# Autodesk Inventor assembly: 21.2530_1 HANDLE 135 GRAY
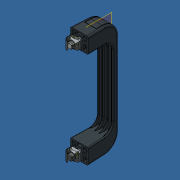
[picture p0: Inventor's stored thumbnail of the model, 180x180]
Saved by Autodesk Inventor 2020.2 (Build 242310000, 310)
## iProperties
Created: 2020-07
Part Number: 21.2530_1 HANDLE 135 GRAY
Document SubType Name: Assembly
Designer: amoles
Author: amoles
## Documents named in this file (5)
- Y:\INVENTOR LIBRARIES\PARTS LIBRARY\HANDLES LOCKS STOPS\21.2530_7 HANDLE 135 GRAY.iam
- Y:\INVENTOR LIBRARIES\PARTS LIBRARY\HANDLES LOCKS STOPS\SUBCOMPONENTS\21.2530_1 HANDLE 135 GRAY.ipt
- Y:\INVENTOR LIBRARIES\PARTS LIBRARY\FASTENING ELEMENTS\SCREWS CAP\21.1202 M8X20.ipt
- Y:\INVENTOR LIBRARIES\PARTS LIBRARY\HANDLES LOCKS STOPS\SUBCOMPONENTS\21.2530_1 HANDLE 135 GRAY END CAP.ipt
- Y:\INVENTOR LIBRARIES\PARTS LIBRARY\FASTENING ELEMENTS\NUTS\21.1351_2 M8 SQUARE NUT POS FXG.ipt
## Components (7 placed, 4 different names)
1. 21.2530_1 HANDLE 135 GRAY:1 — Insert:1, Insert:2, Insert:3, Insert:4, Mate:1, Mate:2, Flush:1, Mate:3, Mate:4, Flush:2
2. 21.1202  M8 x 20:1 — Insert:1
3. 21.1202  M8 x 20:2 — Insert:2
4. 21.1351_2 M8 SQUARE NUT POS FXG:1 — Insert:3
5. 21.1351_2 M8 SQUARE NUT POS FXG:2 — Insert:4
6. 21.2530_1 HANDLE 135 GRAY END CAP:1 — Mate:1, Mate:2, Flush:1
7. 21.2530_1 HANDLE 135 GRAY END CAP:2 — Mate:3, Mate:4, Flush:2
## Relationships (10: Insert 4, Mate 4, Flush 2)
- Insert:1: 21.2530_1 HANDLE 135 GRAY:1 ↔ 21.1202  M8 x 20:1
- Insert:2: 21.2530_1 HANDLE 135 GRAY:1 ↔ 21.1202  M8 x 20:2
- Insert:3: 21.2530_1 HANDLE 135 GRAY:1 ↔ 21.1351_2 M8 SQUARE NUT POS FXG:1
- Insert:4: 21.2530_1 HANDLE 135 GRAY:1 ↔ 21.1351_2 M8 SQUARE NUT POS FXG:2
- Mate:1: 21.2530_1 HANDLE 135 GRAY:1 ↔ 21.2530_1 HANDLE 135 GRAY END CAP:1
- Mate:2: 21.2530_1 HANDLE 135 GRAY:1 ↔ 21.2530_1 HANDLE 135 GRAY END CAP:1
- Flush:1: 21.2530_1 HANDLE 135 GRAY:1 ↔ 21.2530_1 HANDLE 135 GRAY END CAP:1
- Mate:3: 21.2530_1 HANDLE 135 GRAY:1 ↔ 21.2530_1 HANDLE 135 GRAY END CAP:2
- Mate:4: 21.2530_1 HANDLE 135 GRAY:1 ↔ 21.2530_1 HANDLE 135 GRAY END CAP:2
- Flush:2: 21.2530_1 HANDLE 135 GRAY:1 ↔ 21.2530_1 HANDLE 135 GRAY END CAP:2
